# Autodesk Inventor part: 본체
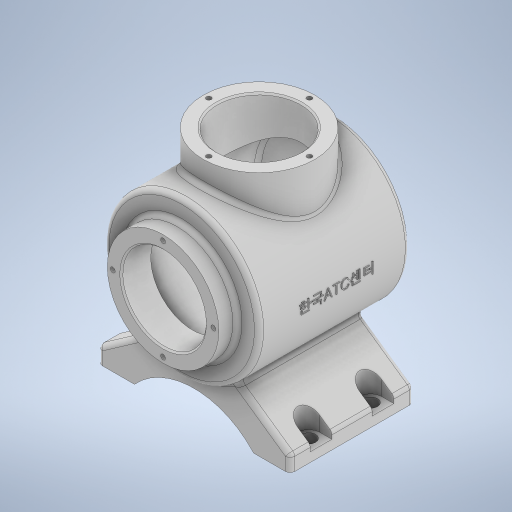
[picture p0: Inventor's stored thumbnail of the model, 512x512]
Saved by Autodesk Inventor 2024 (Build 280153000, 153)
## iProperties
Created: 2023-08
Part Number: 본체
Material: 일반
Document SubType Name: Modeling
Designer: Owner
Density: 1 g/cm^3
Appearance: 기본값
Mass: 480.256 g
Surface Area: 1060.45 cm^2
Volume: 480.256 cm^3
Author: Owner
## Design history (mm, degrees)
sketch "스케치2"
  geometry: L1 (0, 0)-(0, -120); L2 (36, 0)-(36, -12); L3 (36, -12)-(50, -12); L4 (50, -12)-(50, -108.336); L5 (43, -103.887)-(43, -19); L6 (27, 0)-(36, 0); L7 (27, 0)-(27, -19); L8 (27, -19)-(43, -19); A1 r 113 centre (0, -7) between (0, -120) and (50, -108.336); A2 r 106 centre (0, -7) between (0, -113) and (43, -103.887)
  constraints: 16 end point, 4 point on circle, 3 perpendicular, 3 vertical, 2 centre point, 1 horizontal, 1 horizontal alignment, 1 point on line, 1 vertical alignment
  dimensions: "d9" = 120 distance of L1.start L1.end; "d10" = 113 radius of A1; "d11" = 72 diameter of L2 L1; "d12" = 100 diameter of L4 L1; "d13" = 108 distance from line of L1.end L3; "d14" = 7 distance between parallel lines of L4 L5; "d15" = 7 radial gap between concentric circles of A1 A2; "d86" = 54 diameter of L7 L1; "d87" = 19 distance of L6.start L7.end
revolve "회전1" sketch "스케치2" stored, may be unused: angle "d16" = 90 deg
node "작업 평면1"
sketch "스케치3"
  geometry: L1 (-36, 0)-(36, 0) reference; C1 r 36 at (0, -62); 2 further points
  constraints: 1 centre point, 1 midpoint, 1 vertical alignment
  dimensions: "d18" = 62 distance from line of C1.centre L1; "d19" = 72 diameter of C1
extrude "돌출1" join sketch "스케치3" stored distance "d20" = 10; taper "d21" = 0 deg
sketch "스케치4"
  geometry: C1 r 36 at (0, 0) reference; 2 further points
  constraints: 1 coincident
hole "구멍1" sketch "스케치4" at (0, 0) diameter "d22" = 54; stored, may be unused: countersink angle "d26" = 90 deg, drill point angle "d28" = 0 deg; dims "d23" = 8, "d24" = 4, "d25" = 2, "d27" = 40
sketch "스케치5"
  geometry: C1 r 27 at (0, 0) reference; 2 further points
  constraints: 1 horizontal alignment
  dimensions: "d29" = 32.5 distance of C1.centre point (-32.5, 0)
hole "구멍2" sketch "스케치5" at (-32.5, 0) diameter "d30" = 3.242; stored, may be unused: countersink angle "d34" = 90 deg, drill point angle "d36" = 118 deg; dims "d31" = 8, "d32" = 4, "d33" = 2, "d35" = 10
node "작업 평면2"
sketch "스케치6"
  geometry: L1 (38.5, -77)-(62, -77); L2 (62, -77)-(62, -67); L3 (62, -67)-(26.694, -42.278); L4 (0, 0)-(0, -108.924); L5 (-62, -67)-(-26.694, -42.278); L6 (-62, -77)-(-62, -67); L7 (-38.5, -77)-(-62, -77); A1 r 52.096 centre (0, -112.096) between (38.5, -77) and (-38.5, -77); A2 r 50 centre (0, 0) between (26.694, -42.278) and (-26.694, -42.278) reference; 3 further points
  constraints: 14 end point, 4 symmetric about line, 3 point on circle, 1 centre point, 1 horizontal, 1 perpendicular, 1 vertical, 2 other
  dimensions: "d41" = 17 distance from line of L1 point (0, -60); "d42" = 77 distance of L7.start L1.start; "d43" = 10 distance of L1.end L2.end; "d44" = 55 deg angle of L2 L3; "d45" = 77 distance from line of L1 point (0, 0); "d46" = 124 distance between parallel lines of L6 L2
extrude "돌출2" join sketch "스케치6" distance "d47" = 80; taper "d48" = 0 deg
sketch "스케치7"
  geometry: L1 (23.5, 0)-(23.5, -80) reference; L2 (0, 0)-(23.5, 0) reference; 2 further points
  dimensions: "d49" = 8 distance from line of L1 point (15.5, -20); "d50" = 20 distance from line of L2 point (15.5, -20)
hole "구멍3" sketch "스케치7" at (15.5, -20) diameter "d51" = 9; stored, may be unused: countersink angle "d55" = 90 deg, drill point angle "d57" = 0 deg; dims "d52" = 8, "d53" = 4, "d54" = 2, "d56" = 26
node "작업 평면3"
sketch "스케치8"
  geometry: L1 (15.5, -20)-(31.095, -20); L2 (15.5, -27)-(31.095, -27); L3 (31.095, -13)-(15.5, -13); C1 r 4.5 at (15.5, -20) reference; A1 r 7 centre (15.5, -20) between (15.5, -13) and (15.5, -27); A2 r 7 centre (31.095, -20) between (31.095, -27) and (31.095, -13); 2 further points
  constraints: 8 end point, 4 point on circle, 4 tangent, 2 centre point, 1 horizontal, 1 midpoint, 1 parallel
  dimensions: "d59" = 14 distance between parallel lines of L2 L3; "d60" = 15.5952 distance of L1.start L1.end
extrude "돌출3" cut sketch "스케치8" distance "d61" = 22.5; taper "d62" = 0 deg
node "작업 평면5"
sketch "스케치9"
  geometry: C1 r 27 at (0, 0) reference; 2 further points
  constraints: 1 vertical alignment
  dimensions: "d64" = 32.5 distance of point (0, 0) point (0, 32.5)
hole "구멍4" sketch "스케치9" at (0, 32.5) diameter "d65" = 3.242; stored, may be unused: countersink angle "d69" = 90 deg, drill point angle "d71" = 118 deg; dims "d66" = 8, "d67" = 4, "d68" = 2, "d70" = 10
fillet "모깎기1" dims "d75" = 3
fillet "모깎기2" dims "d76" = 3
fillet "모깎기3" dims "d77" = 3
fillet "모깎기4" dims "d78" = 3
fillet "모깎기5" dims "d79" = 3
chamfer "모따기1" distance "d80" = 1; stored, may be unused: second distance "d81" = 2, angle "d82" = 45 deg
node "작업 평면8"
sketch "스케치10"
  geometry: L1 (-36, 60.168)-(36, 60.168) reference; 2 further points
  constraints: 1 vertical alignment, 1 other
  dimensions: "d83" = 62 distance from line of L1 point (0, -1.832)
feature "엠보싱1" sketch "스케치10" dims "d84" = 0.5, "d85" = 0
node "솔리드1"
pattern_circular "원형 패턴1" dims angle "d38" = 360 deg
mirror "미러1"
mirror "미러2"
pattern_circular "원형 패턴2" dims angle "d73" = 360 deg
node "작업 평면4"
node "작업 평면6"
node "작업 평면7"
feature "A9D066F2-1C7D-4E18-AEED-F7BC21143FA4" dims "d22" = 54, "d23" = 8, "d24" = 4, "d25" = 2, "d26" = 90 deg, "d27" = 40, "d28" = 0
other parameters: "d17" = 65, "d58" = -6
